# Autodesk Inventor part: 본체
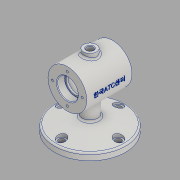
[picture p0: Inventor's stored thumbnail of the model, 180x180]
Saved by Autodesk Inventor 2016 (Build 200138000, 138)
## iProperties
Created: 2018-12
Part Number: 본체
Material: 알루미늄 6061
Document SubType Name: Modeling
Designer: 605-08
Density: 2.7 g/cm^3
Appearance: 알루미늄 - 평지
Mass: 673.24 g
Surface Area: 553.144 cm^2
Volume: 249.348 cm^3
Author: 605-08
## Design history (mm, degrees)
sketch "스케치1"
  geometry: L1 (-35, 30)-(35, 30); L2 (35, 30)-(35, 0); L3 (35, 0)-(-35, 0); L4 (-35, 0)-(-35, 30); L5 (-35, 16)-(-23, 16); L6 (-23, 16)-(-23, 14); L7 (-23, 14)-(-20, 14); L8 (-20, 14)-(-20, 25); L9 (-20, 25)-(20, 25); L10 (20, 25)-(20, 14); L11 (20, 14)-(23, 14); L12 (23, 14)-(23, 16); L13 (23, 16)-(35, 16); 2 further points
  constraints: 26 end point, 10 perpendicular, 2 collinear, 2 parallel, 2 point on line, 1 coincident, 1 horizontal, 1 midpoint
  dimensions: "d0" = 70 distance between parallel lines of L2 L4; "d1" = 12 distance between parallel lines of L6 L4; "d2" = 12 distance between parallel lines of L2 L12; "d3" = 32 diameter of L5 L3; "d4" = 28 diameter of L7 L3; "d5" = 50 diameter of L9 L3; "d6" = 40 distance between parallel lines of L10 L8; "d7" = 60 diameter of L1 L3; "d8" = 3 distance between parallel lines of L12 L10
revolve "회전1" sketch "스케치1" stored, may be unused: angle "d9" = 90 deg
fillet "모깎기1" dims "d10" = 3, "d11" = 0.3
chamfer "모따기1" distance "d12" = 1; stored, may be unused: second distance "d13" = 2, angle "d14" = 45 deg
node "작업 평면1"
sketch "스케치2"
  geometry: C1 r 55 at (0, 0); 1 further point
  constraints: 1 centre point, 1 coincident
  dimensions: "d16" = 110 diameter of C1
extrude "돌출1" join sketch "스케치2" distance "d17" = 22; taper "d18" = 0 deg
sketch "스케치6" dims "d39" = 88
  geometry: L1 (0, 0)-(0, -44); 2 further points
  constraints: 2 coincident, 2 end point, 1 vertical, 1 vertical alignment, 2 other
hole "구멍2" sketch "스케치6" at (0, -44) diameter "d40" = 9; stored, may be unused: countersink angle "d44" = 90 deg, drill point angle "d46" = 0 deg; dims "d41" = 6, "d42" = 14, "d43" = 12, "d45" = 8
node "작업 평면2"
sketch "스케치4"
  geometry: C1 r 10 at (0, 0); 1 further point
  constraints: 1 centre point, 1 coincident
  dimensions: "d26" = 20 diameter of C1
extrude "돌출3" join sketch "스케치4" stored distance "d27" = 10; taper "d28" = 0 deg
hole "구멍1" diameter "d31" = 10; stored, may be unused: countersink angle "d35" = 90 deg, drill point angle "d37" = 0 deg; dims "d29" = 10, "d30" = 10, "d32" = 6, "d33" = 4, "d34" = 2, "d36" = 8
sketch "스케치7" dims "d50" = 46
  geometry: L1 (0, 0)-(-23, 0); 2 further points
  constraints: 2 coincident, 2 end point, 1 horizontal, 1 horizontal alignment, 2 other
hole "구멍3" sketch "스케치7" at (-23, 0) diameter "d51" = 3.242; stored, may be unused: countersink angle "d55" = 90 deg, drill point angle "d57" = 118 deg; dims "d52" = 8, "d53" = 14, "d54" = 12, "d56" = 10
sketch "스케치10"
  geometry: C1 r 12 at (0, 0); 1 further point
  constraints: 1 centre point, 1 coincident
  dimensions: "d68" = 24 diameter of C1
extrude "돌출6" join sketch "스케치10" stored distance "d69" = 10; taper "d70" = 0 deg; dims "d37" = 0
chamfer "모따기3" distance "d71" = 11.52; stored, may be unused: second distance "d72" = 2, angle "d73" = 75 deg
fillet "모깎기2" dims "d74" = 3
fillet "모깎기3" dims "d75" = 3
chamfer "모따기4" distance "d76" = 1; stored, may be unused: second distance "d77" = 2, angle "d78" = 75 deg
node "작업 평면3"
node "작업 평면4"
sketch "스케치12"
  geometry: L1 (-35, -30)-(-35, 30) reference; L2 (-35, 30)-(35, 30) reference; 2 further points
  constraints: 1 other
  dimensions: "d83" = 35 distance from line of L1 point (0, 0); "d84" = 30 distance from line of L2 point (0, 0)
feature "엠보싱2" sketch "스케치12" dims "d0" = 70, "d1" = 12, "d2" = 12, "d3" = 32, "d4" = 28, "d5" = 50, "d6" = 40, "d7" = 60, "d8" = 3, "d85" = 0.5, "d86" = 0
node "솔리드1"
pattern_circular "원형 패턴1" dims angle "d48" = 360 deg
pattern_circular "원형 패턴2" dims angle "d59" = 360 deg
mirror "대칭1"
other parameters: "d15" = -75, "d25" = 37
